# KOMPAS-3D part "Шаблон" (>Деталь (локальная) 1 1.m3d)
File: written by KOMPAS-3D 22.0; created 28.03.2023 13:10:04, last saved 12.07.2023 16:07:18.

Document properties: Автор: Admin; Полное имя файла: C:\Users\yna_n\AppData\Local\Temp\KOMPAS-3D\ktff-b13f-4749-a96a\_Деталь (локальная) 1 1.m3d

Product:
- Part/product: Шаблон
    Масса: 0.449021

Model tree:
1. Эскиз:1
2. Эскиз:24
3. Элемент выдавливания:85
     Расстояние 1 = 156
4. Элемент выдавливания:86
     Расстояние 1 = 50
5. Булева операция:1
